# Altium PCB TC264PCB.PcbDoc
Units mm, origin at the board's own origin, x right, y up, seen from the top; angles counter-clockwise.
Board outline 100.58 x 100.35 mm, 2 copper layers (Top Layer, Bottom Layer); 82 components, 103 nets, 403 pads, 81 vias.
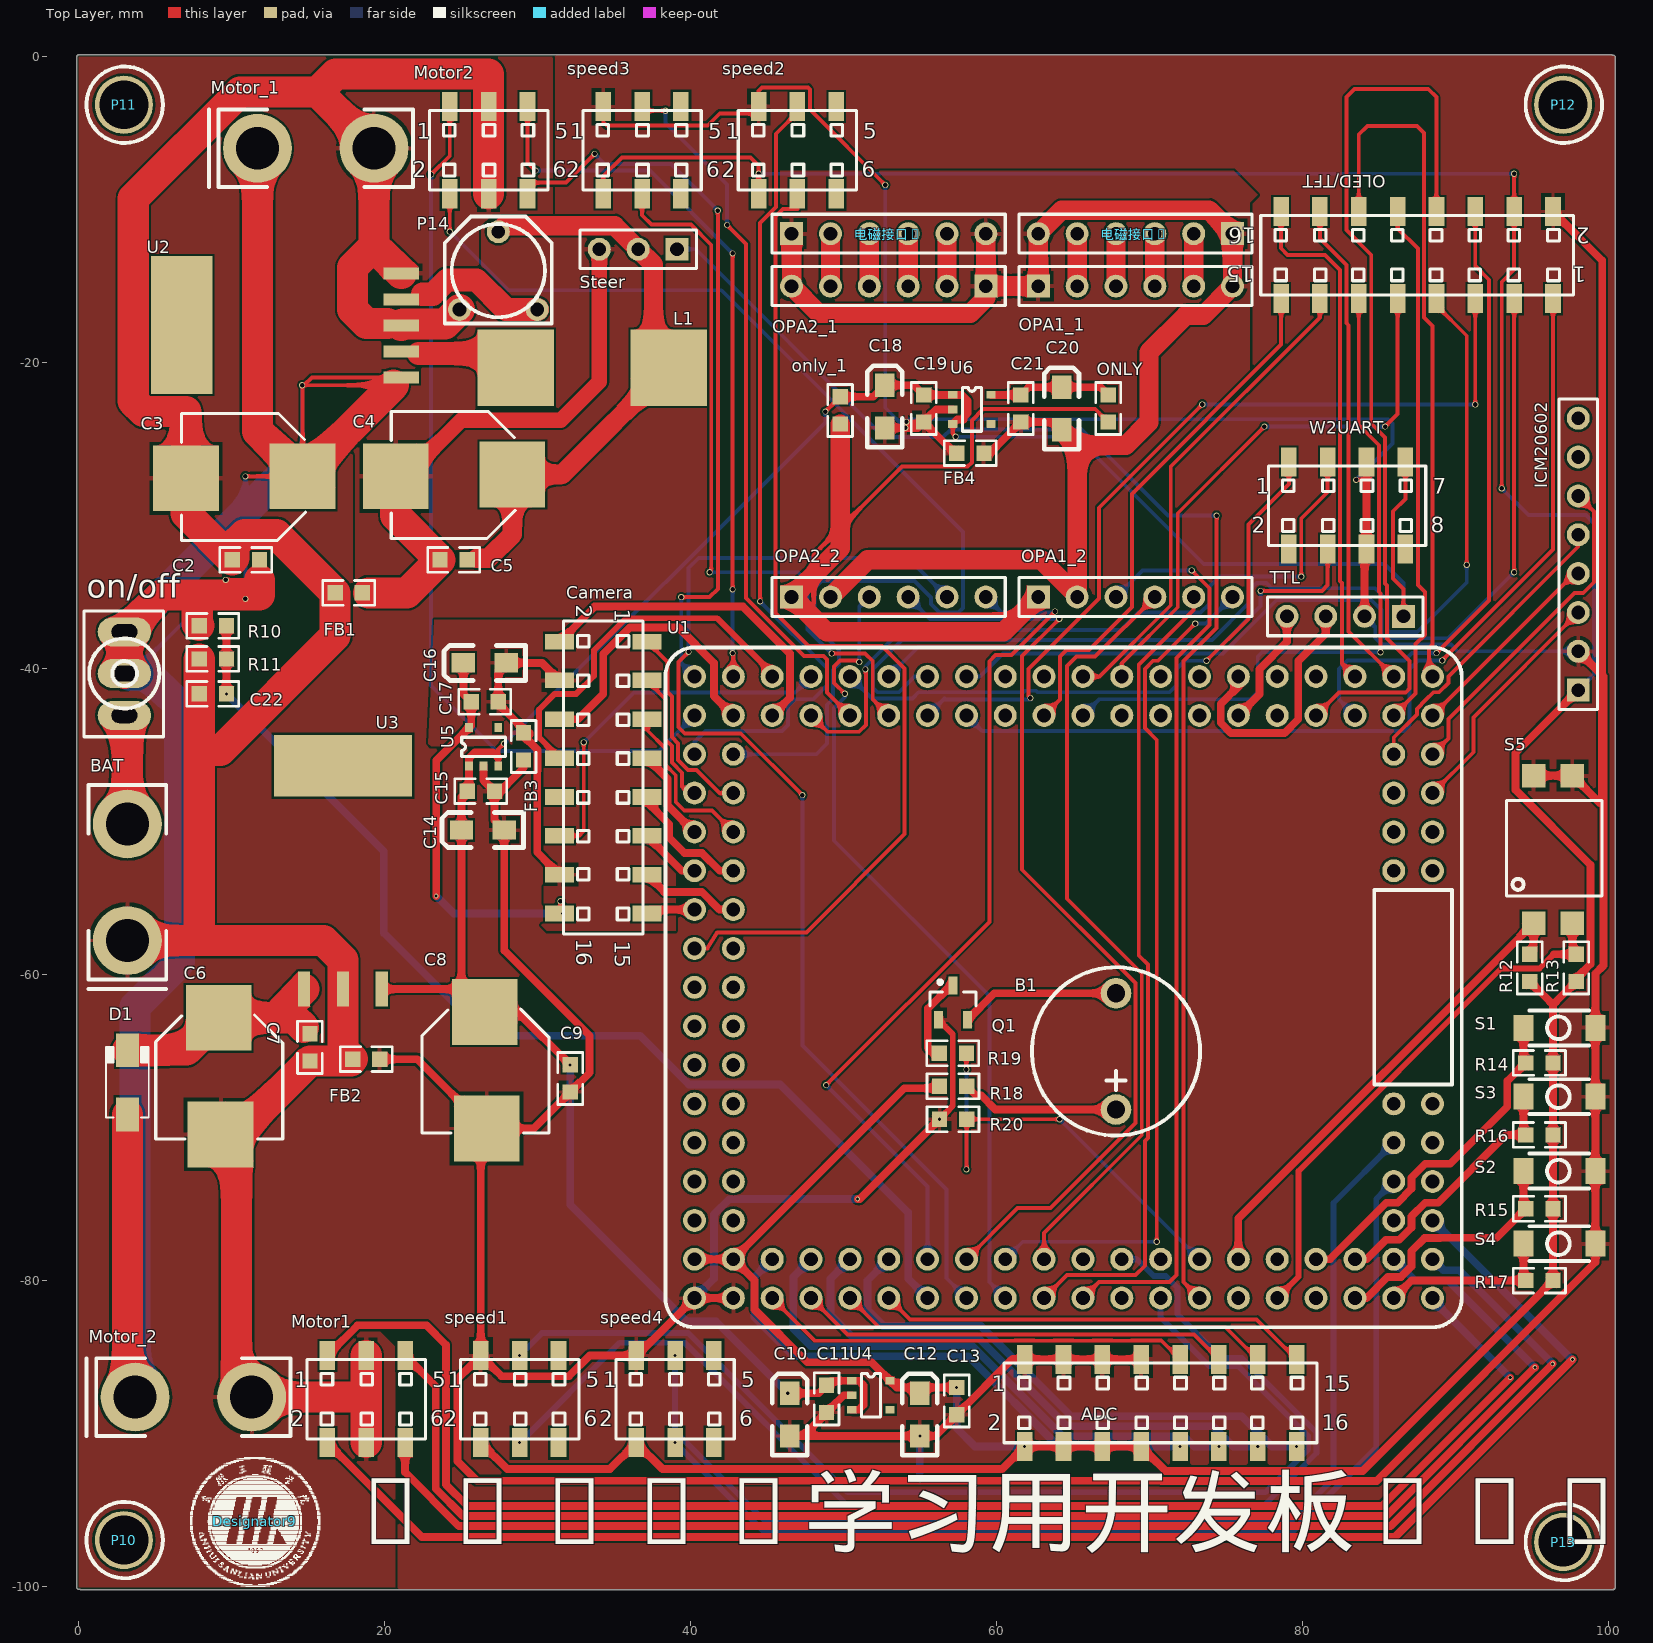
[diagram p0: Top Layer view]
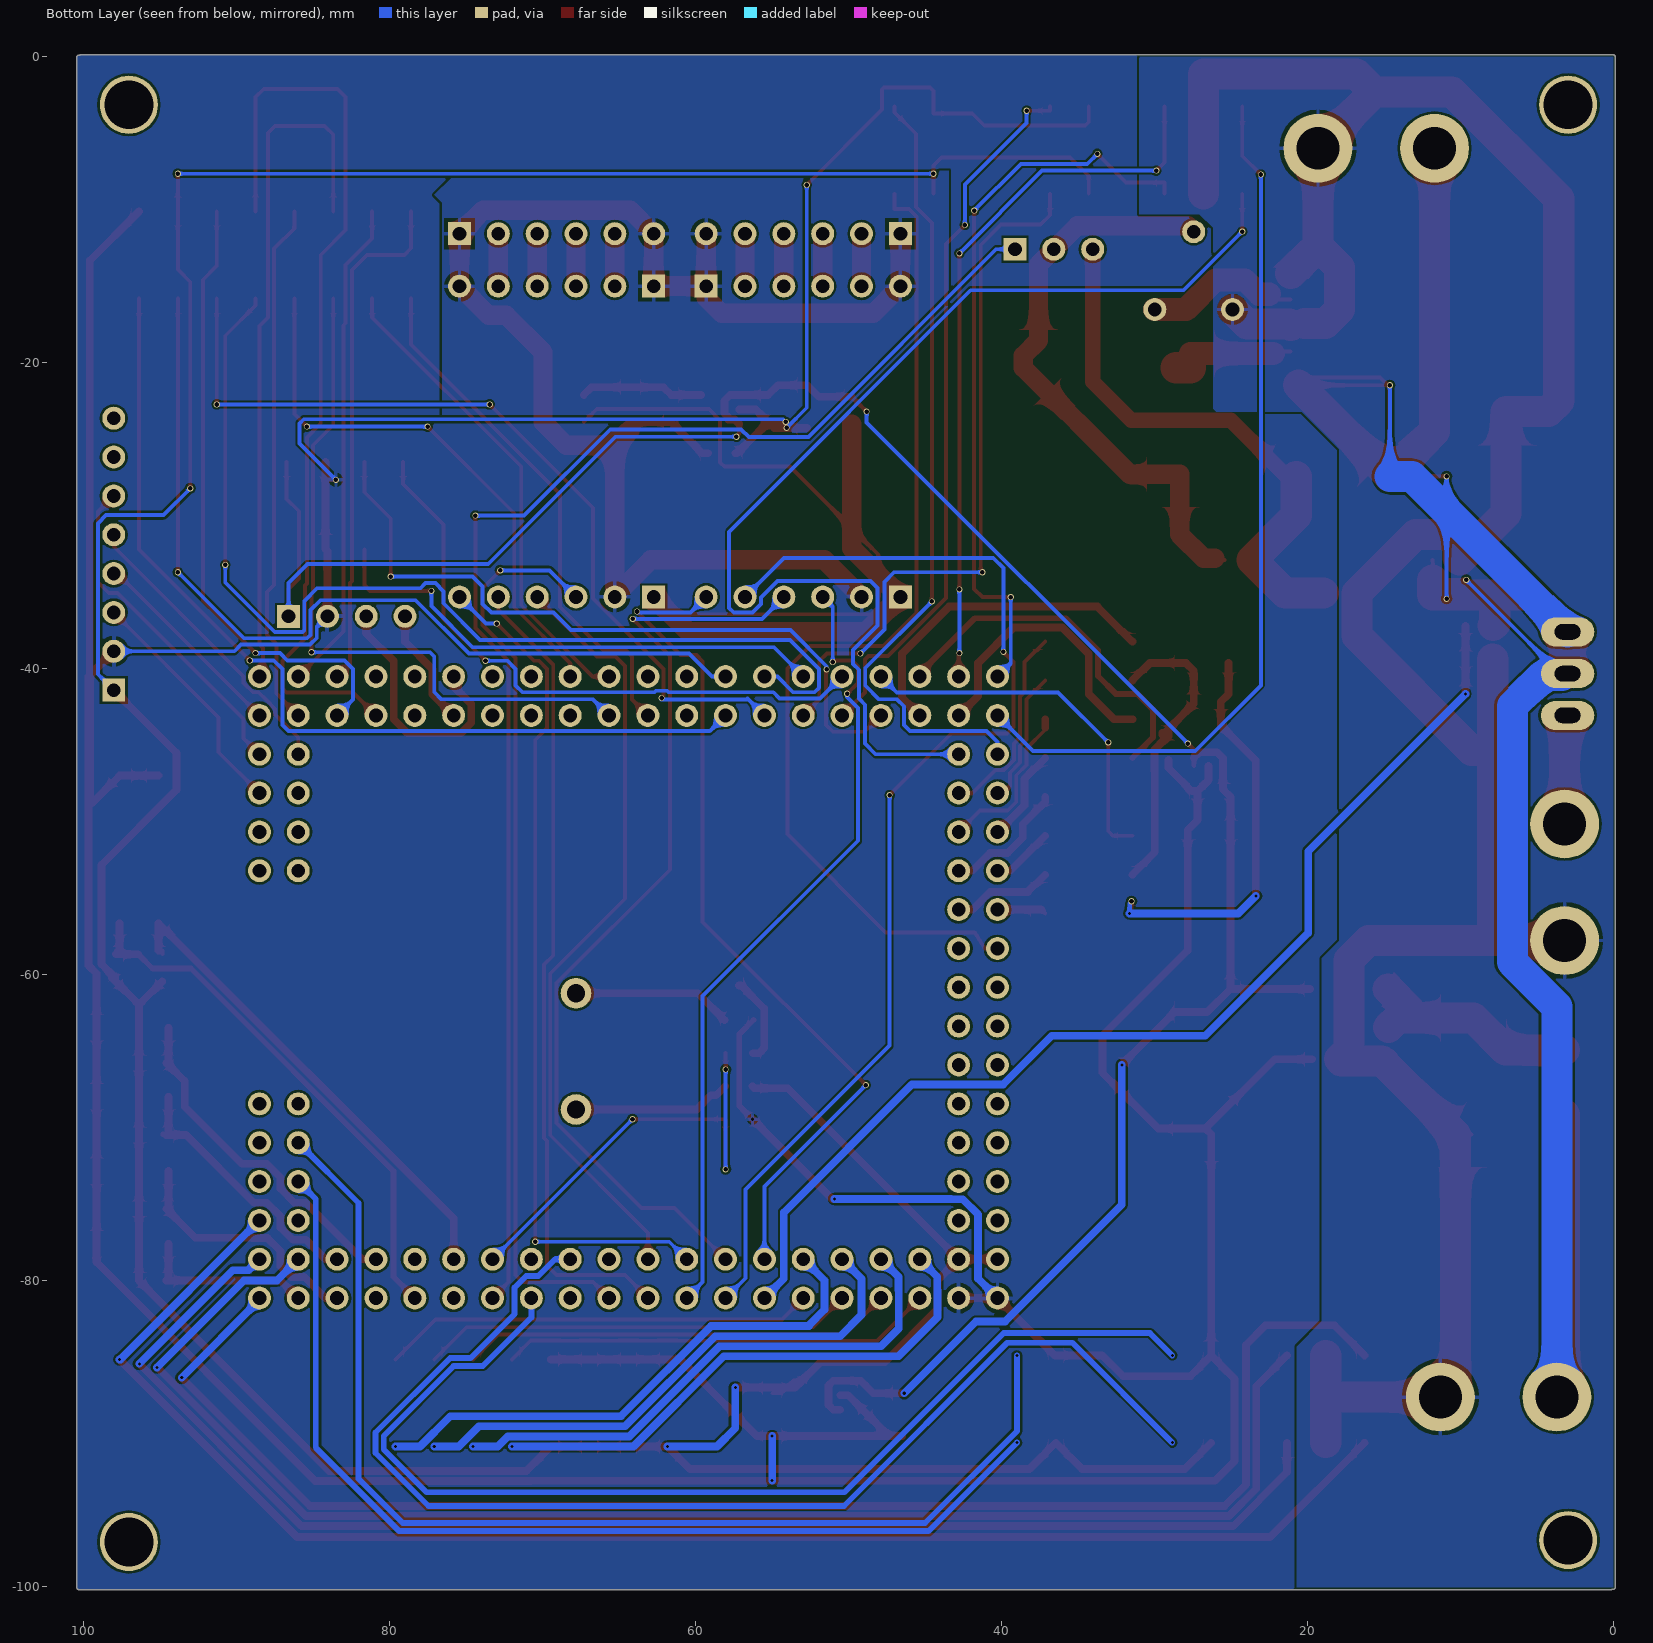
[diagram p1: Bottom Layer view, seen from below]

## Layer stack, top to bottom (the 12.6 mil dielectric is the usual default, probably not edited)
Top Solder: solder mask 0.0102, Solder Resist, Dk 3.5
Top Layer: signal copper 0.0356
Dielectric 1: dielectric 0.32, FR-4, Dk 4.8
Bottom Layer: signal copper 0.0356
Bottom Solder: solder mask 0.0102, Solder Resist, Dk 3.5

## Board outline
-0.127,-100.066 ccw(c0,-100.066) 0.046,-100.185 ccw(c0.127,-100.086) 0.127,-100.213 100.33,-100.213 ccw(c100.33,-100.086) 100.457,-100.086 100.457,-0.01 ccw(c100.33,-0.01) 100.284,0.109 ccw(c100.203,0.01) 100.203,0.137 0,0.137 ccw(c0,0.01) -0.127,0.01

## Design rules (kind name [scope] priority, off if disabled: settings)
Clearance [All] p1: gap=0.152 ignorepadtopadclearanceinfootprint=FALSE
ComponentClearance [All] p1: gap=0 collisioncheckmode=3 verticalgap=0 showdistances=FALSE
HoleSize [All] p1: absolutevalues=TRUE maxlimit=12.7 minlimit=0.025 maxpercent=80.000 minpercent=20.000
HoleToHoleClearance [All] p1: gap=0.051 allowstackedmicrovias=TRUE
MinimumSolderMaskSliver [All] p1: minsoldermaskwidth=0
PolygonConnect [All] p1: connectstyle=Relief reliefconductorwidth=0.254 reliefentries=4 polygonreliefangle="90 Angle" airgapwidth=0.254
RoutingVias [All] p1: holewidth=0.3 width=0.4 viastyle="Through Hole" minholewidth=0.3 minwidth=0.4 maxholewidth=0.3 maxwidth=0.4
SilkToSilkClearance [All] p1: silktosilkclearance=0
SilkToSolderMaskClearance [IsPad] p1: minsilkscreentomaskgap=0 clearancetoexposedcopper=TRUE
SolderMaskExpansion [All] p1: expansion=0.102
Width [All] p1: maxlimit=12.7 minlimit=0.025 preferedwidth=0.254 minimp=50.000000 maximp=50.000000 favimp=50.000000
24 further rules are at their usual default settings.

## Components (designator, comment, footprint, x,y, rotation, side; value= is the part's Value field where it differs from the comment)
ADC "Header 8X2" HDR2.54-M-LS-2x8P 70.739,-88.011 r0 top
B1 "BEEP" 9*11mm有源蜂鸣器 67.818,-65.024 r90 top
BAT "Header 2" 电源端口 3.175,-57.775 r90 top
C2 "Cap" 0603电容_ 11.049,-32.883 r0 top value=0.1uf
C3 "Cap Pol1" 470UF 10.668,-27.422 r0 top value=330uf
C4 "Cap Pol1" 470UF 24.384,-27.295 r0 top value=330uf
C5 "Cap" 0603电容_ 24.638,-32.883 r0 top value=0.1uf
C6 "Cap Pol1" 470UF 9.144,-66.792 r90 top value=220uf
C7 "Cap" 0603电容_ 15.113,-64.633 r90 top value=0.1uf
C8 "Cap Pol1" 470UF 26.543,-66.411 r90 top value=220uf
C9 "Cap" 0603电容_ 32.131,-66.665 r90 top value=0.1uf
C10 "Cap Pol2" 10UF钽电容 46.355,-88.9 r0 top value=10uf
C11 "Cap" 0603电容_ 48.895,-87.617 r90 top value=0.1uf
C12 "Cap Pol2" 10UF钽电容 54.864,-88.9 r0 top value=10uf
C13 "Cap" 0603电容_ 57.404,-87.757 r90 top value=0.1uf
C14 "Cap Pol2" 10UF钽电容 26.543,-50.673 r90 top value=10uf
C15 "Cap" 0603电容_ 26.162,-48.006 r180 top value=0.1uf
C16 "Cap Pol2" 10UF钽电容 26.67,-39.751 r90 top value=10uf
C17 "Cap" 0603电容_ 26.416,-42.164 r180 top value=0.1uf
C18 "Cap Pol2" 10UF钽电容 52.578,-22.987 r0 top value=10uf
C19 "Cap" 0603电容_ 55.245,-22.86 r90 top value=0.1uf
C20 "Cap Pol2" 10UF钽电容 64.135,-23.114 r0 top value=10uf
C21 "Cap" 0603电容_ 61.595,-22.86 r90 top value=0.1uf
C22 "Cap" 0603电容_ 8.89,-41.646 r0 top value=0.1uf
Camera "Header 8X2" HDR2.54-M-LS-2x8P 34.29,-47.117 r270 top
D1 "SS54" in5819_SLFK 3.175,-67.046 r90 top
Designator9 "Comment" 三联logo 11.519,-95.758 r0 top
FB1 "0R" 0603电阻_ 17.653,-35.042 r180 top
FB2 "0R" 0603电阻_ 18.796,-65.532 r180 top
FB3 "0R" 0603电阻_ 29.083,-45.085 r270 top
FB4 "0R" 0603电阻_ 58.293,-25.908 r180 top
ICM20602 "Header 8" HDR1X8 98.044,-41.402 r90 top
L1 "330uH" 330uH 28.575,-20.32 r0 top
Motor1 "Header 3X2" HDR2.54-M-LS-2x3P 18.796,-87.757 r0 top (schematic designator 电机接口1)
Motor2 "Header 3X2" HDR2.54-M-LS-2x3P 26.797,-6.096 r0 top (schematic designator 电机接口2)
Motor_1 "Header 2" 电源端口 11.684,-5.969 r0 top (schematic designator 供电1)
Motor_2 "Header 2" 电源端口 3.683,-87.63 r0 top (schematic designator 供电2)
OLED/TFT "Header 8X2" HDR2.54-M-LS-2x8P 87.503,-12.954 r180 top
on/off "Header 3" 小扭子开关 3.048,-40.259 r270 top
ONLY "0R" 0603电阻_ 67.31,-22.987 r90 top
only_1 "0R" 0603电阻_ 49.784,-23.114 r90 top
OPA1_1 "Header 6" HDR1X6 62.738,-14.986 r0 top
OPA1_2 "Header 6" HDR1X6 62.738,-35.306 r0 top
OPA2_1 "Header 6" HDR1X6 59.309,-14.986 r180 top
OPA2_2 "Header 6" HDR1X6 46.609,-35.306 r0 top
P10 "SMB" 螺丝孔 2.921,-97.028 r0 top
P11 "SMB" 螺丝孔 2.921,-3.175 r0 top
P12 "SMB" 螺丝孔 97.028,-3.175 r0 top
P13 "SMB" 螺丝孔 97.028,-97.155 r0 top
P14 "10K可调" 白兰可调电阻 27.432,-11.43 r0 top
Q1 "S8050" SI2302 57.15,-61.839 r90 top
R10 "200K" 0603电阻_ 8.763,-37.201 r180 top
R11 "100K" 0603电阻_ 8.763,-39.36 r0 top
R12 "4.7K" 0603电阻_ 94.869,-59.563 r270 top
R13 "4.7K" 0603电阻_ 97.917,-59.563 r270 top
R14 "4.7K" 0603电阻_ 95.504,-65.776 r0 top
R15 "4.7K" 0603电阻_ 95.504,-75.311 r0 top
R16 "4.7K" 0603电阻_ 95.504,-70.485 r0 top
R17 "4.7K" 0603电阻_ 95.504,-80.01 r0 top
R18 "10R" 0603电阻_ 57.166,-67.3 r180 top
R19 "4.7K" 0603电阻_ 57.15,-65.141 r0 top
R20 "10K" 0603电阻_ 57.166,-69.459 r0 top
S1 "" 3*4*2贴片轻触按键 94.465,-63.483 r0 top
S2 "" 3*4*2贴片轻触按键 94.465,-72.851 r0 top
S3 "" 3*4*2贴片轻触按键 94.465,-67.985 r0 top
S4 "" 3*4*2贴片轻触按键 94.465,-77.597 r0 top
S5 "拨码开关" 2pin拨码开关2.54_SMT 95.123,-56.642 r90 top
speed1 "Header 3X2" HDR2.54-M-LS-2x3P 28.829,-87.757 r0 top (schematic designator 编码器1)
speed2 "Header 3X2" HDR2.54-M-LS-2x3P 46.99,-6.096 r0 top (schematic designator 编码器2)
speed3 "Header 3X2" HDR2.54-M-LS-2x3P 36.83,-6.096 r0 top (schematic designator 编码器3)
speed4 "Header 3X2" HDR2.54-M-LS-2x3P 38.989,-87.757 r0 top (schematic designator 编码器4)
Steer "Header 3" HDR1X3 39.116,-12.573 r180 top
TTL "TTL" HDR1X4 86.614,-36.576 r180 top
U1 "TC264_CoreBoard" TC264_CoreBoard 40.259,-81.153 r90 top
U2 "LM2596S-ADJ" TO263-5 21.082,-20.955 r90 top
U3 "LM2940" LM2940-5.0 14.732,-60.95 r0 top
U4 "RT9013-33" SOT-23-5 50.546,-86.554 r0 top
U5 "RT9013-33" SOT-23-5 25.517,-46.355 r90 top
U6 "RT9013-33" SOT-23-5 57.15,-22.098 r0 top
W2UART "W2UART" HDR2.54-M-LS-2x4P 82.931,-29.337 r0 top
电磁接口1 "Header 6" HDR1X6 75.438,-11.557 r180 top
电磁接口2 "Header 6" HDR1X6 46.609,-11.557 r0 top

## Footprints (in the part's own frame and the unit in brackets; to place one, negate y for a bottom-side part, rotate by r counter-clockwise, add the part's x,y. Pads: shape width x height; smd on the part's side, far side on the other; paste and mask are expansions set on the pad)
2pin拨码开关2.54_SMT [mm]
  rect 1.54x1.54 smd: 1(0,0) 2(0,-2.54) 3(9.652,-2.54) 4(9.652,0)
  silkscreen extent 1.78,-4.47 8.03,1.78, body extent 0.12,-4.9 9.19,2.16, height 4.45
3*4*2贴片轻触按键 [mm]
  rect 1.3x1.7 smd: 1(0,0) 2(4.699,0)
  silkscreen extent 0.38,-1.14 4.28,1.14, body extent -0.12,-1.14 4.78,1.14, height 2
9*11mm有源蜂鸣器 [mm]
  round 2 hole 1.2: 1(-3.8,0) 2(3.8,0)
  silkscreen extent -5.5,-5.5 5.5,5.5
10UF钽电容 [mil]
  rect 50x60 smd: 1(5,60) 2(5,-50)
  silkscreen extent -40,-100 50,110, body extent -26,-58 36,68, height 63
330uH [mm]
  rect 5x5 smd: 1(0,0) 2(10,0)
470UF [mm]
  rect 4.3x4.3 smd: 1(3.962,0) 2(-3.658,-0.127)
  silkscreen extent -3.96,-4.19 4.15,4.11, body extent -5,-4.41 4.7,4.09, height 10.3
0603电容_ [mm]
  rect 1x1 smd: 1(-1.016,0) 2(0.762,0)
  silkscreen extent -1.83,-0.81 1.57,0.81, body extent -0.92,-0.38 0.68,0.42, height 0.3
0603电阻_ [mm]
  rect 1x1 smd: 1(0.889,0) 2(-0.889,0)
  silkscreen extent -1.7,-0.81 1.7,0.81, body extent -0.8,-0.4 0.8,0.4, height 0.3
HDR1X3 [mm] "Connector; Header; 3 Position"
  rect 1.5x1.5 hole 0.9: 1(0,0)
  round 1.5 hole 0.9: 2(2.54,0) 3(5.08,0)
  silkscreen extent -1.27,-1.27 6.35,1.27
HDR1X4 [mm] "Connector; Header; 4 Position"
  rect 1.5x1.5 hole 0.9: 1(0,0)
  round 1.5 hole 0.9: 2(2.54,0) 3(5.08,0) 4(7.62,0)
  silkscreen extent -1.27,-1.27 8.89,1.27
HDR1X6 [mm] "Connector; Header; 6 Position"
  rect 1.5x1.5 hole 0.9: 1(0,0)
  round 1.5 hole 0.9: 2(2.54,0) 3(5.08,0) 4(7.62,0) 5(10.16,0) 6(12.7,0)
  silkscreen extent -1.27,-1.27 13.97,1.27
HDR1X8 [mm] "Connector; Header; 8 Position"
  rect 1.5x1.5 hole 0.9: 1(0,0)
  round 1.5 hole 0.9: 2(2.54,0) 3(5.08,0) 4(7.62,0) 5(10.16,0) 6(12.7,0) 7(15.24,0) 8(17.78,0)
  silkscreen extent -1.27,-1.27 19.05,1.27
HDR2.54-M-LS-2x3P [mm] "脚距：2.54mm，贴片双排母"
  rect 1.02x1.9 smd: 1(-2.54,2.85) 2(-2.54,-2.85) 3(0,2.85) 4(0,-2.85) 5(2.54,2.85) 6(2.54,-2.85)
  silkscreen extent -3.87,-2.6 3.87,2.6, body extent -3.84,-3.2 3.84,3.2, height 5.15
HDR2.54-M-LS-2x4P [mm] "脚距：2.54mm，贴片双排母"
  rect 1.02x1.9 smd: 1(-3.81,2.85) 2(-3.81,-2.85) 3(-1.27,2.85) 4(-1.27,-2.85) 5(1.27,2.85) 6(1.27,-2.85) 7(3.81,2.85) 8(3.81,-2.85)
  silkscreen extent -5.15,-2.6 5.14,2.6, body extent -5.11,-3.2 5.11,3.2, height 5.15
HDR2.54-M-LS-2x8P [mm] "脚距：2.54mm，贴片双排母"
  rect 1.02x1.9 smd: 1(-8.89,2.85) 2(-8.89,-2.85) 3(-6.35,2.85) 4(-6.35,-2.85) 5(-3.81,2.85) 6(-3.81,-2.85) 7(-1.27,2.85) 8(-1.27,-2.85) 9(1.27,2.85) 10(1.27,-2.85) 11(3.81,2.85) 12(3.81,-2.85) 13(6.35,2.85) 14(6.35,-2.85) 15(8.89,2.85) 16(8.89,-2.85)
  silkscreen extent -10.23,-2.6 10.22,2.6, body extent -10.19,-3.2 10.19,3.2, height 5.15
in5819_SLFK [mm] "JEDEC DO214 variation AC. SMA"
  rect 2.2x1.5 smd: 1(-2.1,0) 2(2.1,0)
  silkscreen extent -2.3,-1.4 2.3,1.4, body extent -2.6,-1.3 2.6,1.3, height 2.42
LM2940-5.0 [mm]
  rect 9x4 smd: 0(2.54,14.605)
  rect 0.8x2.3 smd: 1(0,0) 2(2.54,0) 3(5.08,0)
  body extent -2.46,-0.29 7.54,15.38, height 4.78
SI2302 [mm] "MOSFET-N"
  rect 1.15x0.6 smd: 1(-1.128,0.934) 2(-1.128,-0.966) 3(1.122,-0.016)
  silkscreen extent -0.2,-1.52 1.47,1.48, body extent -0.7,-1.52 0.7,1.48, height 1.1
SOT-23-5 [mm]
  rect 0.6x0.5 smd: 1(0,0) 2(0,-0.95) 3(0,-1.9) 4(2.5,-1.9) 5(2.5,0)
  silkscreen extent 0.63,-2.38 1.87,0.48, body extent 0.25,-2.45 2.25,0.6, height 0.51
TC264_CoreBoard [mm] "逐飞科技TC264核心板"
  round 1.5 hole 0.9: 1(0,0) 2(2.54,0) 3(0,-2.54) 4(2.54,-2.54) 5(0,-5.08) 6(2.54,-5.08) 7(0,-7.62) 8(2.54,-7.62) 9(0,-10.16) 10(2.54,-10.16) 11(0,-12.7) 12(2.54,-12.7) 13(0,-15.24) 14(2.54,-15.24) 15(0,-17.78) 16(2.54,-17.78) 17(0,-20.32) 18(2.54,-20.32) 19(0,-22.86) 20(2.54,-22.86) 21(0,-25.4) 22(2.54,-25.4) 23(0,-27.94) 24(2.54,-27.94) 25(0,-30.48) 26(2.54,-30.48) 27(0,-33.02) 28(2.54,-33.02) 29(0,-35.56) 30(2.54,-35.56) 31(0,-38.1) 32(2.54,-38.1) 33(0,-40.64) 34(2.54,-40.64) 35(0,-43.18) 36(2.54,-43.18) 37(0,-45.72) 38(2.54,-45.72) 39(0,-48.26) 40(2.54,-48.26) 41(5.08,-48.26) 42(5.08,-45.72) 43(7.62,-48.26) 44(7.62,-45.72) 45(10.16,-48.26) 46(10.16,-45.72) 47(12.7,-48.26) 48(12.7,-45.72) 49(27.94,-45.72) 50(27.94,-48.26) 51(30.48,-45.72) 52(30.48,-48.26) 53(33.02,-45.72) 54(33.02,-48.26) 55(35.56,-45.72) 56(35.56,-48.26) 57(38.1,-48.26) 58(40.64,-48.26) 59(38.1,-45.72) 60(40.64,-45.72) 61(38.1,-43.18) 62(40.64,-43.18) 63(38.1,-40.64) 64(40.64,-40.64) 65(38.1,-38.1) 66(40.64,-38.1) 67(38.1,-35.56) 68(40.64,-35.56) 69(38.1,-33.02) 70(40.64,-33.02) 71(38.1,-30.48) 72(40.64,-30.48) 73(38.1,-27.94) 74(40.64,-27.94) 75(38.1,-25.4) 76(40.64,-25.4) 77(38.1,-22.86) 78(40.64,-22.86) 79(38.1,-20.32) 80(40.64,-20.32) 81(38.1,-17.78) 82(40.64,-17.78) 83(38.1,-15.24) 84(40.64,-15.24) 85(38.1,-12.7) 86(40.64,-12.7) 87(38.1,-10.16) 88(40.64,-10.16) 89(38.1,-7.62) 90(40.64,-7.62) 91(38.1,-5.08) 92(40.64,-5.08) 93(38.1,-2.54) 94(40.64,-2.54) 95(38.1,0) 96(40.64,0) 97(35.56,-2.54) 98(35.56,0) 99(33.02,-2.54) 100(33.02,0) 101(30.48,-2.54) 102(30.48,0) 103(27.94,-2.54) 104(27.94,0) 105(25.4,-2.54) 106(25.4,0) 107(22.86,-2.54) 108(22.86,0) 109(20.32,-2.54) 110(20.32,0) 111(17.78,-2.54) 112(17.78,0) 113(15.24,-2.54) 114(15.24,0) 115(12.7,-2.54) 116(12.7,0) 117(10.16,-2.54) 118(10.16,0) 119(7.62,-2.54) 120(7.62,0) 121(5.08,-2.54) 122(5.08,0)
  silkscreen extent -1.91,-50.16 42.55,1.91
TO263-5 [mm]
  rect 9x4 smd: 0(3.429,14.351)
  rect 0.8x2.3 smd: 1(0,0) 2(1.7,0) 3(3.4,0) 4(5.1,0) 5(6.8,0)
  body extent -1.57,-0.54 8.43,15.13, height 4.83
三联logo [mm]
  silkscreen extent -4.24,-4.24 4.27,4.19
小扭子开关 [mm]
  oval 1.9x3.5 hole 1 slot 1.7 at 90 deg: 1(2.794,-0.063) 2(0.064,-0.063) 3(-2.667,-0.064)
  silkscreen extent -4.04,-2.71 4.19,2.49, body extent -4.14,-2.81 4.29,2.6, height 24
电源端口 [mm]
  round 4.5 hole 2.8: 1(0,0) 2(7.62,0)
  silkscreen extent -3.17,-2.54 10.16,2.54
白兰可调电阻 [mm]
  round 1.5 hole 0.9: 1(-2.54,-5.08) 2(2.54,-5.08) 3(0,0)
  silkscreen extent -3.51,-6.01 3.49,0.99, body extent -3.51,-6.01 3.5,0.99, height 5.84
螺丝孔 [mm]
  round 3.8 hole 3.2: 0(0.025,0.051)
  silkscreen extent -2.42,-2.45 2.58,2.55, body extent -2.72,-2.75 2.88,2.85, height 2.37

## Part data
ADC Camera OLED/TFT: "Header, 8-Pin, Dual row"
B1: library part "Header 2", "Header, 2-Pin"
BAT Motor_1 Motor_2: "Header, 2-Pin"
C2 C5 C7 C9 C11 C13 C15 C17 C19 C21 C22: "Capacitor"
C3 C4 C6 C8: "Polarized Capacitor (Radial)"
C10 C12 C14 C16 C18 C20: "Polarized Capacitor (Axial)"
D1: library part "Diode 1N5404", "3 Amp General Purpose Rectifier"
FB1 FB2 FB3 FB4 ONLY only_1 R10 R11 R12 R13 R14 R15 R16 R17 R18 R19 R20: library part Res2, "Resistor"
ICM20602: "Header, 8-Pin"
Motor1 Motor2 speed1 speed2 speed3 speed4: "Header, 3-Pin, Dual row"
on/off Steer: "Header, 3-Pin"
OPA1_1 OPA1_2 OPA2_1 OPA2_2 电磁接口1 电磁接口2: "Header, 6-Pin"
P10 P11 P12 P13: "SMB Straight Connector"
P14: library part "Header 3", "Header, 3-Pin"
Q1: library part 2N3904, "NPN General Purpose Amplifier"
S1 S2 S3 S4: library part SW-PB, "Switch"
S5: library part "SW DIP-2", "DIP Switch, 2 Position, SPST"
TTL: library part "Header 4", "Header, 4-Pin"
U1: "逐飞科技TC264核心板"
U2: library part LM2596S
W2UART: library part "Header 4X2", "Header, 4-Pin, Dual row"

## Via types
v1: diameter 0.4, hole 0.3, Top Layer to Bottom Layer, 58 vias
v2: diameter 0.3/0.1 (per signal layer), hole 0.2, Top Layer to Bottom Layer, 23 vias

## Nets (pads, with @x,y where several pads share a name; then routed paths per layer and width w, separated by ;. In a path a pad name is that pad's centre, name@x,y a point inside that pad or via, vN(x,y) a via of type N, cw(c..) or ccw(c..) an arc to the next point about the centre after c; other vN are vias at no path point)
00.0: Camera.1 U1.99 | length 13.1
  Top Layer w0.254: Camera.1 38.481,-39.568 38.481,-41.533 38.776,-41.828 38.776,-44.478 39.182,-44.885 39.182,-45.972 39.833,-46.622 40.386,-46.622 41.897,-48.133 U1.99
00.1: Camera.3 U1.100 | length 8.9
  Top Layer w0.254: Camera.3 38.369,-41.996 38.369,-44.647 38.776,-45.053 38.776,-46.14 39.436,-46.801 39.436,-47.691 39.878,-48.133 U1.100
00.2: Camera.5 U1.101 | length 11.2
  Top Layer w0.254: 37.14,-43.856 37.14,-43.992 38.369,-45.221 38.369,-46.309 39.03,-46.969 39.03,-48.719 39.587,-49.276 41.402,-49.276 U1.101
  Top Layer w0.508: 37.14,-43.856 Camera.5 ; U1.101@42.418,-50.673 U1.101
00.3: Camera.7 U1.102 | length 6.1
  Top Layer w0.508: Camera.7 38.496,-47.203 38.496,-48.94 40.23,-50.673 U1.102
00.4: Camera.9 U1.103 | length 8.4
  Top Layer w0.508: Camera.9 37.14,-48.697 38.608,-50.165 38.608,-51.054 39.611,-52.057 40.754,-52.057 41.91,-53.213 U1.103
00.5: Camera.11 U1.104 | length 4.1
  Top Layer w0.508: Camera.11 39.426,-53.213 U1.104
00.6: Camera.13 U1.105 | length 6.6
  Top Layer w0.508: Camera.13 38.27,-54.597 40.738,-54.597 41.894,-55.753 U1.105
00.7: Camera.15 U1.106 | length 3.2
  Top Layer w0.254: Camera.15 Camera.15@37.394,-55.753
  Top Layer w0.508: Camera.15@37.394,-55.753 U1.106
00.9: speed2.4 U1.108 | length 66.3
  Top Layer w0.254: U1.108 41.097,-58.293 41.758,-57.242 47.574,-57.242 54,-50.815 54,-39.995 52.522,-38.517 47.721,-38.517 45.568,-36.363 45.568,-10.42 46.041,-9.947 46.99,-9.947 speed2.4
02.0: Camera.12 U1.90 | length 24.2
  Top Layer w0.254: Camera.12 32.715,-50.927 33.02,-50.622 v1(33.02,-44.821)
  Bottom Layer w0.254: v1(33.02,-44.821) 36.297,-41.544 46.848,-41.544 U1.90
02.1: Camera.2 U1.91 | length 21.8
  Top Layer w0.508: Camera.2 33.726,-35.941 43.434,-35.941 46.495,-39.002 46.495,-41.897 U1.91
02.2: Camera.8 U1.92 | length 24.1
  Top Layer w0.381: Camera.8 30.099,-44.506 30.099,-42.672 31.125,-41.646 32.522,-41.646 33.693,-40.475 33.693,-38.795 35.785,-36.703 41.738,-36.703 45.339,-40.304 U1.92
02.3: Camera.6 U1.93 | length 19
  Top Layer w0.508: Camera.6 32.639,-43.307 34.29,-41.656 34.29,-39.042 36.022,-37.311 39.216,-37.311 41.529,-39.624 41.529,-41.783 U1.93
02.4: Motor2.5 U1.94 | length 47.2
  Top Layer w0.254: Motor2.5 29.337,-6.899 v1(29.87,-7.432) ; v1(42.748,-38.979) 42.799,-39.03 U1.94 ; v1(42.748,-34.813) v1(42.748,-12.842)
  Bottom Layer w0.254: v1(29.87,-7.432) 37.338,-7.432 v1(42.748,-12.842) ; v1(42.748,-38.979) v1(42.748,-34.813)
02.5: Motor2.1 U1.95 | length 58.3
  Top Layer w0.254: v1(23.038,-7.686) 24.257,-6.467 Motor2.1
  Bottom Layer w0.254: v1(23.038,-7.686) 23.038,-41.087 27.33,-45.38 37.932,-45.38 U1.95
02.6: Motor2.6 U1.96 | length 48.4
  Top Layer w0.254: Motor2.6 29.337,-8.22 31.852,-8.22 v1(33.731,-6.34) ; v1(39.395,-35.321) 41.25,-35.321 41.783,-34.788 v1(41.783,-10.048)
  Bottom Layer w0.254: v1(33.731,-6.34) 34.392,-7 38.735,-7 v1(41.783,-10.048) ; v1(39.395,-35.321) 39.395,-39.649 U1.96
02.7: Motor2.2 U1.97 | length 77.9
  Top Layer w0.254: v1(24.257,-11.42) Motor2.2
  Bottom Layer w0.254: v1(24.257,-11.42) 28.092,-15.255 42.012,-15.255 57.81,-31.054 57.81,-36.033 57.506,-36.337 56.286,-36.337 55.728,-35.779 55.728,-35.349 54.633,-34.255 48.565,-34.255 48.108,-34.712 48.108,-37.176 49.708,-38.776 49.708,-39.69 49.327,-40.071 49.327,-41.951 48.92,-42.357 48.92,-44.897 48.225,-45.593 U1.97
02.8: speed2.3 U1.98 | length 52.4
  Top Layer w0.254: v1(44.552,-35.601) 44.552,-10.861 45.593,-9.82 45.593,-5.019 46.99,-3.622 speed2.3
  Bottom Layer w0.254: U1.98 40.259,-44.796 40.97,-44.084 45.974,-44.084 46.38,-43.678 46.38,-42.459 46.838,-42.002 48.006,-42.002 48.908,-41.099 48.908,-39.958 v1(44.552,-35.601)
10.1: speed3.4 U1.85 | length 47
  Top Layer w0.254: speed3.4 36.83,-10.353 37.44,-10.963 40.03,-10.963 41.354,-12.287 41.354,-33.591 v1(41.25,-33.696) ; v1(49.225,-39.004) 51.41,-39.004 51.918,-39.512 51.918,-42.012 U1.85
  Bottom Layer w0.254: v1(41.25,-33.696) 47.015,-33.696 47.65,-34.331 47.65,-37.43 v1(49.225,-39.004)
10.2: U1.86 W2UART.4 | length 34.1
  Top Layer w0.254: v1(77.279,-34.915) 81.28,-34.915 81.661,-34.534 W2UART.4
  Bottom Layer w0.254: U1.86 54.874,-38.598 74.577,-38.598 77.279,-35.896 v1(77.279,-34.915)
10.3: speed3.3 U1.87 | length 47.1
  Top Layer w0.254: speed3.3 36.83,-3.521 v1(38.354,-3.521) ; v1(42.393,-10.988) 43.637,-12.233 43.637,-35.39 47.43,-39.182 48.692,-39.182 48.92,-39.411 48.92,-41.554 U1.87
  Bottom Layer w0.254: v1(38.354,-3.521) 38.354,-4.308 42.393,-8.347 v1(42.393,-10.988)
10.5: U1.88 W2UART.1 | length 40.9
  Top Layer w0.254: v1(73.74,-39.484) 76.479,-36.744 76.479,-30.572 79.121,-27.93 W2UART.1
  Bottom Layer w0.254: U1.88 51.855,-41.949 54.512,-41.949 54.918,-41.542 61.773,-41.542 61.876,-41.439 62.589,-41.439 62.693,-41.542 71.323,-41.542 71.768,-41.097 71.768,-40.02 72.305,-39.484 v1(73.74,-39.484)
10.6: U1.89 W2UART.3 | length 47.9
  Top Layer w0.254: U1.89 48.951,-44.125 51.013,-44.125 51.46,-43.678 51.46,-40.071 v1(51.435,-40.046) ; v1(79.934,-33.975) 79.934,-30.191 81.661,-28.463 W2UART.3
  Bottom Layer w0.254: v1(51.435,-40.046) 51.435,-39.843 53.797,-37.48 68.148,-37.48 69.293,-36.335 73.355,-36.335 73.927,-35.763 73.927,-34.622 74.574,-33.975 v1(79.934,-33.975)
11.9: OLED/TFT.1 U1.81 | length 62.3
  Top Layer w0.254: v1(89.148,-39.462) 96.393,-32.217 OLED/TFT.1
  Bottom Layer w0.254: U1.81 59.07,-44.084 86.614,-44.084 87.02,-43.678 87.02,-40.02 87.579,-39.462 v1(89.148,-39.462)
11.10: OLED/TFT.3 U1.82 | length 59.5
  Top Layer w0.254: v1(93.853,-33.696) OLED/TFT.3
  Bottom Layer w0.254: U1.82 58.915,-40.513 60.423,-39.004 74.828,-39.004 78.308,-35.525 84.531,-35.525 85.178,-36.172 85.178,-37.785 85.405,-38.012 89.537,-38.012 v1(93.853,-33.696)
11.11: OLED/TFT.5 U1.83 | length 56
  Top Layer w0.254: v1(62.223,-41.919) 62.09,-41.785 62.09,-40.02 66.7,-35.41 66.7,-29.479 v1(73.457,-22.723) ; v1(91.313,-22.723) OLED/TFT.5
  Bottom Layer w0.254: U1.83 56.601,-41.951 56.674,-42.024 62.217,-42.024 62.223,-42.017 v1(62.223,-41.919) ; v1(73.457,-22.723) v1(91.313,-22.723)
11.12: OLED/TFT.7 U1.84 | length 70.1
  Top Layer w0.254: OLED/TFT.7 88.773,-16.246 90.754,-18.227 v1(90.754,-33.213)
  Bottom Layer w0.254: U1.84 54.651,-40.513 53.621,-41.542 52.222,-41.542 51.93,-41.25 51.93,-40.02 53.835,-38.115 74.084,-38.115 76.479,-35.72 76.479,-34.94 77.013,-34.407 77.648,-34.407 77.978,-34.737 84.746,-34.737 85.585,-35.575 85.585,-37.48 85.71,-37.605 87.518,-37.605 90.754,-34.37 v1(90.754,-33.213)
13.0: OLED/TFT.9 U1.74 | length 36.8
  Top Layer w0.254: U1.74 68.199,-39.639 71.857,-35.982 71.857,-29.835 v1(77.521,-24.171) ; v1(85.42,-24.171) 86.233,-23.358 OLED/TFT.9
  Bottom Layer w0.254: v1(77.521,-24.171) v1(85.42,-24.171)
13.1: OLED/TFT.11 U1.75 | length 46.2
  Top Layer w0.254: OLED/TFT.11 83.693,-24.069 85.014,-25.39 85.014,-34.969 85.115,-35.071 v1(85.115,-38.928)
  Bottom Layer w0.254: U1.75 66.71,-42.002 76.606,-42.002 77.089,-41.519 77.089,-39.208 77.368,-38.928 v1(85.115,-38.928)
13.2: OLED/TFT.13 U1.76 | length 31.8
  Top Layer w0.254: U1.76 66.741,-40.513 71.399,-35.855 71.399,-26.787 81.153,-17.033 OLED/TFT.13
13.3: OLED/TFT.15 U1.77 | length 34.5
  Top Layer w0.254: U1.77 64.16,-42.012 64.16,-39.208 64.595,-38.773 66.043,-38.773 68.859,-35.956 68.859,-28.565 78.613,-18.811 OLED/TFT.15
14.0: TTL.4 U1.67 | length 7.8
  Top Layer w0.508: U1.67 77.203,-41.669 77.203,-40.034 78.994,-38.243 TTL.4
14.1: TTL.3 U1.68 | length 16.7
  Top Layer w0.508: U1.68 75.819,-41.148 74.663,-42.304 74.663,-43.532 75.34,-44.209 78.838,-44.209 79.743,-43.305 79.743,-39.497 81.534,-37.706 TTL.3
15.0: OLED/TFT.12 U1.58 | length 45.8
  Top Layer w0.254: OLED/TFT.12 83.693,-5.07 84.252,-4.511 87.503,-4.511 87.96,-4.968 87.96,-17.033 88.519,-17.592 88.519,-38.43 88.291,-38.658 88.291,-39.941 88.519,-39.941 U1.58
15.1: OLED/TFT.10 U1.59 | length 34.5
  Top Layer w0.254: U1.59 87.415,-41.617 87.415,-38.381 88.012,-37.784 88.012,-34.992 87.554,-34.534 87.554,-12.538 86.233,-11.217 OLED/TFT.10
15.2: OLED/TFT.14 U1.60 | length 32.4
  Top Layer w0.254: OLED/TFT.14 81.153,-11.877 82.88,-13.604 82.88,-17.389 83.033,-17.541 83.033,-37.567 U1.60
15.3: OLED/TFT.6 U1.61 | length 40.9
  Top Layer w0.254: v1(88.773,-38.979) 92.202,-35.55 92.202,-14.57 91.313,-13.681 OLED/TFT.6
  Bottom Layer w0.254: U1.61 82.398,-42.012 82.398,-40.02 82.956,-39.462 86.698,-39.462 87.181,-38.979 v1(88.773,-38.979)
15.4: OLED/TFT.16 U1.62 | length 33.8
  Top Layer w0.254: OLED/TFT.16 78.613,-12.512 79.045,-12.944 81.483,-12.944 82.474,-13.935 82.474,-34.28 82.601,-34.407 82.601,-39.675 U1.62
15.5: OLED/TFT.8 U1.63 | length 61
  Top Layer w0.254: U1.63 82.408,-41.544 86.766,-41.544 87.008,-41.302 87.008,-39.487 85.547,-38.026 85.547,-34.559 85.42,-34.432 85.42,-24.882 84.506,-23.968 84.506,-12.944 82.88,-11.318 82.88,-2.632 83.414,-2.098 88.24,-2.098 88.773,-2.632 OLED/TFT.8
20.0: speed4.4 U1.44 | length 68.4
  Bottom Layer w0.381: v2(38.989,-90.607) 44.775,-96.393 79.375,-96.393 84.836,-90.932 84.836,-74.676 U1.44
20.3: speed4.3 U1.46 | length 75.3
  Bottom Layer w0.381: v2(38.989,-84.907) 38.989,-89.853 44.996,-95.86 79.146,-95.86 82.042,-92.964 82.042,-74.93 U1.46
20.11: ICM20602.3 U1.54 | length 15.8
  Top Layer w0.254: U1.54 91.186,-45.466 91.186,-43.18 ICM20602.3
20.12: ICM20602.5 U1.55 | length 19.6
  Top Layer w0.254: U1.55 85.979,-44.509 87.49,-42.998 87.49,-42.627 88.093,-42.024 88.574,-41.542 88.945,-41.542 89.548,-40.939 89.548,-40.515 98.044,-32.02 ICM20602.5
20.13: ICM20602.6 U1.56 | length 22
  Top Layer w0.254: U1.56 89.548,-44.564 89.548,-43.294 97.79,-35.052 98.37,-35.052 99.073,-34.349 99.073,-29.731 ICM20602.6
20.14: ICM20602.4 U1.57 | length 13.4
  Top Layer w0.254: U1.57 97.79,-33.782 ICM20602.4
21.2: Motor1.5 U1.38 | length 98.3
  Top Layer w0.508: Motor1.5 23.343,-86.914 23.343,-93.619 25.126,-95.402 85.491,-95.402 v2(95.209,-85.684)
  Bottom Layer w0.508: U1.38 87.363,-79.997 89.522,-79.997 v2(95.209,-85.684)
21.3: Motor1.1 U1.39 | length 99.2
  Top Layer w0.508: Motor1.1 18.232,-82.931 22.733,-82.931 24.003,-84.201 24.003,-93.345 25.4,-94.742 85.217,-94.742 v2(93.599,-86.36)
  Bottom Layer w0.508: U1.39 88.519,-81.28 v2(93.599,-86.36)
21.4: Motor1.6 U1.40 | length 93.5
  Top Layer w0.508: Motor1.6 21.336,-92.546 24.853,-96.063 85.764,-96.063 v2(96.374,-85.452)
  Bottom Layer w0.508: U1.40 89.242,-79.336 90.258,-79.336 v2(96.374,-85.452)
21.5: Motor1.2 U1.41 | length 101.7
  Top Layer w0.508: Motor1.2 22.423,-96.774 86.059,-96.774 v2(97.667,-85.165)
  Bottom Layer w0.508: U1.41 97.611,-85.165 v2(97.667,-85.165)
22.0: R14.2 S1.1 U1.34 | length 22.8
  Top Layer w0.508: U1.34 81.804,-78.613 85.5,-74.917 86.231,-74.917 87.135,-74.012 87.135,-73.281 88.04,-72.377 89.675,-72.377 93.408,-68.644 93.408,-66.967 94.599,-65.776 R14.2 94.465,-65.626 S1.1
22.1: R15.2 S2.1 U1.35 | length 16.7
  Top Layer w0.508: U1.35 84.201,-81.153 85.585,-79.769 86.458,-79.769 87.135,-79.092 87.135,-78.092 87.998,-77.229 88.998,-77.229 89.011,-77.216 92.71,-77.216 R15.2 94.465,-75.161 S2.1
22.2: R16.2 S3.1 U1.36 | length 18.1
  Top Layer w0.254: R16.2@94.465,-70.335 94.465,-70.399 94.869,-70.399 94.869,-70.485 R16.2
  Top Layer w0.508: U1.36 84.201,-78.613 85.471,-77.343 86.344,-77.343 87.135,-76.552 87.135,-75.821 88.04,-74.917 88.884,-74.917 93.316,-70.485 R16.2 ; R16.2@94.465,-70.335 S3.1
22.3: R17.2 S4.1 U1.37 | length 11.7
  Top Layer w0.254: R17.2@94.465,-79.86 94.615,-79.86 94.615,-79.997 R17.2
  Top Layer w0.508: U1.37 86.008,-81.153 87.165,-79.997 94.615,-79.997 R17.2 ; R17.2@94.465,-79.86 S4.1
33.6: speed1.4 U1.24 | length 80.4
  Bottom Layer w0.381: v2(28.829,-90.607) 35.362,-84.074 39.624,-84.074 50.292,-94.742 77.462,-94.742 80.924,-91.28 80.924,-89.949 76.04,-85.065 74.709,-85.065 71.832,-82.187 71.832,-80.468 71.07,-79.706 70.286,-79.706 69.193,-78.613 U1.24
33.7: speed1.3 U1.25 | length 72.7
  Bottom Layer w0.381: v2(28.829,-84.907) 30.297,-83.439 39.847,-83.439 50.261,-93.853 77.597,-93.853 80.391,-91.059 80.391,-90.17 75.819,-85.598 73.914,-85.598 70.739,-82.423 70.739,-81.915 U1.25
33.9: Steer.1 U1.27 | length 95.4
  Top Layer w0.254: U1.27 72.238,-80.112 72.238,-39.487 74.397,-37.328 v1(74.397,-29.987)
  Bottom Layer w0.254: Steer.1 40.345,-12.573 52.629,-24.857 56.515,-24.857 57.023,-24.349 65.583,-24.349 71.222,-29.987 v1(74.397,-29.987)
33.10: R19.1 R20.1 U1.28 | length 29.9
  Top Layer w0.254: v1(58.039,-72.736) 58.055,-72.72 R20.1 v1(64.125,-69.459) ; v1(58.039,-66.208) R19.1
  Bottom Layer w0.254: v1(58.039,-72.736) v1(58.039,-66.208) ; v1(64.125,-69.459) U1.28
33.12: R12.2 S5.1 U1.30 | length 32.3
  Top Layer w0.254: R12.2 94.869,-58.42 R12.2@95.123,-58.42
  Top Layer w0.508: U1.30 75.819,-75.946 S5.1 R12.2@95.123,-58.42
33.13: R13.2 S5.2 U1.31 | length 35.2
  Top Layer w0.254: R13.2@97.663,-58.42 97.917,-58.42 R13.2
  Top Layer w0.381: U1.31 79.756,-79.756 79.756,-72.853 93,-59.609 95.509,-59.609 96.444,-58.674
  Top Layer w0.508: 96.444,-58.674 R13.2 ; R13.2@97.663,-58.42 S5.2
A0: OPA1_2.3 U1.21 | length 59.9
  Top Layer w0.254: U1.21 66.71,-80.102 71.323,-80.102 71.78,-79.644 71.78,-39.309 73.939,-37.15 73.939,-34.737 v1(72.771,-33.569)
  Bottom Layer w0.254: OPA1_2.3 69.555,-33.569 v1(72.771,-33.569)
A1: OPA1_2.4 U1.20 | length 51.1
  Top Layer w0.254: U1.20 63.119,-76.895 69.504,-70.51 69.504,-59.929 64.618,-55.042 64.618,-39.822 65.227,-39.212 66.452,-39.212 OPA1_2.4
A2: OPA1_2.5 U1.19 | length 53
  Top Layer w0.254: U1.19 64.618,-79.654 69.095,-79.654 69.71,-79.039 69.71,-70.879 69.91,-70.678 69.91,-59.344 69.303,-58.737 69.303,-39.754 72.898,-36.16 OPA1_2.5
A3: OPA1_2.6 U1.18 | length 55.8
  Top Layer w0.254: v1(70.485,-77.47) 70.485,-44.657 69.71,-43.881 69.71,-40.02 70.246,-39.484 70.565,-39.484 v1(73,-37.049)
  Bottom Layer w0.254: U1.18 61.722,-77.47 v1(70.485,-77.47) ; v1(73,-37.049) 73.695,-37.049 OPA1_2.6
A4: OPA2_2.3 U1.17 | length 52.9
  Top Layer w0.254: v1(50.089,-41.639) 49.378,-40.927 49.378,-39.868 49.784,-39.462 50.927,-39.462 v1(51.029,-39.563)
  Bottom Layer w0.254: v1(50.089,-41.639) 50.089,-41.849 49.378,-42.56 49.378,-51.247 59.538,-61.407 59.538,-80.112 U1.17 ; v1(51.029,-39.563) 51.029,-35.966 OPA2_2.3
A5: OPA2_2.4 U1.16 | length 62.3
  Top Layer w0.254: U1.16 61.376,-75.276 63.525,-75.276 69.097,-69.704 69.097,-60.564 61.683,-53.149 61.683,-39.17 v1(64.11,-36.744)
  Bottom Layer w0.254: OPA2_2.4 55.667,-36.744 v1(64.11,-36.744)
A6: OPA2_2.5 U1.15 | length 76.2
  Top Layer w0.254: v1(39.878,-38.903) 39.218,-39.563 39.218,-43.83 39.624,-44.237 43.282,-44.237 v1(47.315,-48.271)
  Bottom Layer w0.254: v1(39.878,-38.903) 39.878,-33.416 40.538,-32.756 54.219,-32.756 OPA2_2.5 ; v1(47.315,-48.271) 47.315,-64.633 56.744,-74.061 56.744,-79.858 U1.15
A7: OPA2_2.6 U1.14 | length 56.9
  Top Layer w0.254: v1(48.87,-67.224) 59.538,-56.556 59.538,-39.512 59.944,-39.106 60.985,-39.106 v1(63.83,-36.261)
  Bottom Layer w0.254: v1(48.87,-67.224) 55.499,-73.853 U1.14 ; OPA2_2.6 60.34,-36.337 63.754,-36.337 v1(63.83,-36.261)
A8: C22.2 R10.2 R11.1 U1.13 | length 72.3
  Top Layer w0.508: v2(9.652,-41.646) R11.1 R10.2
  Bottom Layer w0.508: v2(9.652,-41.646) 19.939,-51.933 19.939,-57.277 26.67,-64.008 36.703,-64.008 39.878,-67.183 45.847,-67.183 54.229,-75.565 54.229,-79.883 U1.13
A10: ADC.16 U1.12 | length 35.7
  Bottom Layer w0.508: U1.12 51.575,-79.997 51.575,-81.915 52.578,-82.918 52.578,-82.982 58.987,-82.982 64.885,-88.88 76.042,-88.88 78.023,-90.861 v2(79.629,-90.861)
A11: ADC.15 U1.11 | length 28.3
  Top Layer w0.254: U1.11 54.356,-82.55 77.018,-82.55 ADC.15
A12: ADC.14 U1.10 | length 35.7
  Bottom Layer w0.508: U1.10 49.149,-79.883 49.149,-82.245 50.546,-83.642 58.713,-83.642 64.611,-89.54 74.162,-89.54 75.483,-90.861 v2(77.089,-90.861)
A13: ADC.13 U1.9 | length 28.3
  Top Layer w0.254: U1.9 52.324,-83.058 74.986,-83.058 ADC.13
A16: ADC.12 U1.8 | length 36
  Bottom Layer w0.508: U1.8 46.736,-79.756 46.736,-80.647 46.723,-80.661 46.723,-83.146 47.879,-84.303 58.44,-84.303 64.338,-90.201 72.283,-90.201 72.943,-90.861 v2(74.549,-90.861)
A17: ADC.11 U1.7 | length 28.4
  Top Layer w0.254: U1.7 50.267,-83.541 61.04,-83.541 61.055,-83.525 62.643,-83.525 62.658,-83.541 63.58,-83.541 63.595,-83.525 65.183,-83.525 65.198,-83.541 66.12,-83.541 66.135,-83.525 67.723,-83.525 67.738,-83.541 68.66,-83.541 68.675,-83.525 72.913,-83.525 ADC.11
A20: ADC.10 U1.6 | length 35.6
  Bottom Layer w0.508: U1.6 44.196,-79.756 44.196,-80.647 44.183,-80.661 44.183,-82.41 46.736,-84.963 58.166,-84.963 64.064,-90.861 v2(72.009,-90.861)
A21: ADC.9 U1.5 | length 28.4
  Top Layer w0.254: U1.5 48.133,-83.947 61.208,-83.947 61.223,-83.932 62.475,-83.932 62.49,-83.947 63.748,-83.947 63.763,-83.932 65.015,-83.932 65.03,-83.947 66.288,-83.947 66.303,-83.932 67.555,-83.932 67.57,-83.947 68.828,-83.947 68.843,-83.932 70.78,-83.932 ADC.9
GND5V: ADC.1 ADC.3 ADC.5 ADC.7 C8.2 C9.1 C10.2 C11.1 C12.2 C13.1 C14.2 C15.1 C18.2 C19.1 FB2.2 FB3.1 FB4.1 ICM20602.2 OLED/TFT.2 Q1.1 R20.2 S1.2 S2.2 S3.2 S4.2 S5.3 S5.4 speed1.1 speed2.1 speed3.1 speed4.1 TTL.2 U1.1 U1.3 U4.2 U5.2 U6.2 W2UART.5 W2UART.6 | length 435.2
  Top Layer w0.254: speed3.1 34.29,-4.257 34.519,-4.486 41.123,-4.486 41.91,-3.698 44.45,-3.698 speed2.1 44.45,-2.225 44.679,-1.997 47.676,-1.997 47.803,-2.124 47.803,-3.444 v1(52.73,-8.372) ; C18.2 v1(54.051,-24.257) ; v1(54.102,-23.866) 55.362,-23.866 FB4.1 ; v1(83.515,-27.651) 84.074,-27.651 84.201,-27.524 W2UART.5 ; ICM20602.2 99.47,-40.288 99.47,-48.797
  Top Layer w0.381: Q1.1 57.15,-63.901 57.15,-68.586 v2(56.277,-69.459)
  Top Layer w0.508: FB2.2 22.133,-65.532 C8.2 ; U5.2 26.467,-47.295 C15.1 ; FB3.1 29.083,-46.482 27.559,-48.006 C15.1 ; U1.3 U1.1 36.505,-84.907 speed4.1 33.404,-84.907 32.047,-86.263 27.645,-86.263 speed1.1 ; C10.2 47.358,-90.17 ; U4.2 50.025,-87.504 C11.1 47.358,-90.17 ; v2(50.927,-74.676) 51.06,-74.676 v2(56.277,-69.459) ; C18.2 54.864,-24.257 C19.1 ; U6.2 56.073,-23.048 C19.1 ; FB4.1 57.277,-25.908 C19.1 ; ADC.7 ADC.5 ADC.3 ADC.1 61.016,-85.161 C13.1 56.007,-90.17 v2(54.991,-90.17) 47.358,-90.17 ; TTL.2 84.074,-32.314 W2UART.6 W2UART.5 ; S5.4 S5.3 99.47,-48.797 ; OLED/TFT.2 99.607,-13.318 99.607,-40.211 99.5,-40.318 ; ICM20602.2 99.5,-40.318 ; speed1.1 24.765,-86.431 24.765,-91.821 26.035,-93.091 v2(54.991,-93.091) 70.765,-93.091 70.79,-93.116 84.861,-93.116 99.164,-78.814 S4.2 S2.2 S3.2 S1.2 99.164,-59.936 99.695,-59.405 99.695,-40.513 99.5,-40.318 ; speed1.1 26.289,-70.45 C8.2 ; C8.2 29.743,-70.069 C9.1 33.401,-66.411 33.401,-64.008 27.813,-58.42 C14.2 27.178,-49.911 C15.1
  Bottom Layer w0.254: v1(52.73,-8.372) 52.73,-22.936 v1(54.051,-24.257) ; v1(54.102,-23.866) 54.277,-23.691 85.623,-23.691 85.9,-23.968 85.9,-25.266 v1(83.515,-27.651) ; TTL.2 84.772,-37.274 84.772,-37.988 85.213,-38.43 89.729,-38.43 90.162,-38.862 ICM20602.2
  Bottom Layer w0.508: U1.1 41.529,-79.883 41.529,-75.692 42.532,-74.689 43.278,-74.689 43.291,-74.676 v2(50.927,-74.676) ; v2(54.991,-93.091) v2(54.991,-90.17)
GND_6.5V: C4.2 C5.1 FB1.2 Steer.3 | length 37.2
  Top Layer w0.254: FB1.2 FB1.2@18.948,-35.042
  Top Layer w1.016: C4.2 21.346,-27.422 25.019,-23.749 31.52,-23.749 34.036,-21.233 Steer.3
  Top Layer w2.032: FB1.2@18.948,-35.042 21.463,-35.042 C5.1 20.726,-29.987 C4.2
GNDBAT: BAT.1 C2.1 C3.2 C6.2 C7.1 C22.1 FB1.1 FB2.1 Motor1.3 Motor1.4 Motor2.3 Motor2.4 Motor_1.2 Motor_2.2 P14.1 R11.2 U2.3 U2.5 U3.2 | length 206.2
  Top Layer w0.254: BAT.1 5.613,-57.775 5.74,-57.648 7.874,-57.648 ; C6.2 14.072,-65.649 C7.1 ; U2.3@20.193,-17.423 20.193,-17.555 U2.3
  Top Layer w2.032: BAT.1 15.992,-57.775 17.272,-59.055 U3.2 17.272,-64.897 FB2.1 17.79,-65.649 C7.1 10.312,-70.45 10.312,-86.639 Motor_2.2 18.542,-87.63 18.796,-87.884 ; 7.874,-57.648 7.874,-45.339 ; R11.2 C22.1 7.874,-45.339 ; Motor1.4 18.796,-87.884 ; Motor1.3 18.796,-87.884 ; U2.3@20.193,-17.423 18.82,-17.423 17.907,-16.51 17.907,-13.774 19.304,-12.377 ; U2.3 21.181,-17.456 23.946,-17.456 P14.1 ; U2.5 19.304,-12.377 ; Motor2.4 Motor2.3 26.797,-1.128 16.779,-1.128 15.621,-2.286 ; 7.874,-45.339 9.271,-45.339 16.764,-37.846 FB1.1 12.937,-31.215 10.827,-31.215 10.143,-31.899 10.143,-32.773 C2.1 7.01,-29.86 C3.2 7.01,-23.194 4.247,-23.194 3.563,-22.51 3.563,-9.256 10.533,-2.286 15.621,-2.286 ; 15.621,-2.286 Motor_1.2 19.304,-12.377
GNDCAM: C16.2 C17.1 Camera.4 Camera.14 FB3.2 | length 20.5
  Top Layer w0.254: FB3.2 FB3.2@29.464,-44.196
  Top Layer w0.508: FB3.2 29.083,-44.399 29.989,-45.306 29.989,-46.66 29.972,-46.677 29.972,-51.999 Camera.14 ; FB3.2@29.464,-44.196 29.464,-44.323 27.432,-42.291 C17.1 27.432,-40.132 C16.2 30.297,-39.624 Camera.4
GNDOP: C20.2 C21.1 FB4.2 OPA1_1.1 OPA1_1.6 OPA1_2.2 OPA2_1.1 OPA2_1.6 OPA2_2.2 电磁接口1.1 电磁接口1.6 电磁接口2.1 电磁接口2.6 | length 98.5
  Top Layer w0.508: FB4.2 59.563,-25.908 C21.1 63.754,-23.876 C20.2
  Top Layer w1.27: 电磁接口2.1 OPA2_1.6 48.387,-16.764 58.293,-16.764 59.309,-15.748 OPA2_1.1 ; OPA2_2.2 51.572,-32.883 62.929,-32.883 OPA1_2.2@65.278,-35.232 ; 电磁接口2.6 OPA2_1.1 ; C20.2 65.278,-25.4 ; OPA1_2.2 OPA1_2.2@65.278,-35.232 ; OPA2_1.1 OPA1_1.1 电磁接口1.6 64.275,-10.02 73.901,-10.02 电磁接口1.1 OPA1_1.6 73.533,-16.891 72.39,-16.891 69.977,-19.304 69.977,-23.876 68.453,-25.4 65.278,-25.4 ; OPA1_2.2@65.278,-35.232 65.278,-25.4
NetB1_1: B1.1 R18.2 | length 10.4
  Top Layer w0.508: R18.2 58.647,-67.892 58.997,-67.892 59.929,-68.824 B1.1
NetB1_2: B1.2 Q1.2 | length 10.4
  Top Layer w0.508: Q1.2 59.859,-61.224 B1.2
NetBAT_2: BAT.2 on/off.1 | length 7.9
  Top Layer w0.254: on/off.1 3.48,-43.053 3.48,-43.145 3.175,-43.145 on/off.1@3.175,-43.244
  Top Layer w2.032: BAT.2 on/off.1@3.175,-43.244
NetC6_1: C6.1 C7.2 D1.2 U3.1 | length 17
  Top Layer w0.254: C7.2@14.707,-63.465 14.275,-63.465 14.275,-63.871 C7.2
  Top Layer w2.032: D1.2 7.028,-64.946 C6.1 12.852,-62.83 ; C7.2@14.707,-63.465 14.072,-62.83 12.852,-62.83 ; U3.1 12.852,-62.83
NetL1_1: L1.1 U2.2 | length 8.6
  Top Layer w0.254: U2.2 22.225,-19.255 U2.2@22.225,-19.387 ; L1.1@27.642,-20.32 L1.1@27.642,-19.387
  Top Layer w1.524: U2.2@22.225,-19.387 L1.1@27.642,-19.387
  Top Layer w2.032: L1.1@27.642,-20.32 L1.1
NetOPA1_1_2: OPA1_1.2 电磁接口1.5 | length 3.4
  Top Layer w1.27: OPA1_1.2 电磁接口1.5
NetOPA1_1_3: OPA1_1.3 电磁接口1.4 | length 3.4
  Top Layer w1.27: OPA1_1.3 电磁接口1.4
NetOPA1_1_4: OPA1_1.4 电磁接口1.3 | length 3.4
  Top Layer w1.27: OPA1_1.4 电磁接口1.3
NetOPA1_1_5: OPA1_1.5 电磁接口1.2 | length 3.4
  Top Layer w1.27: OPA1_1.5 电磁接口1.2
NetOPA2_1_2: OPA2_1.2 电磁接口2.5 | length 3.4
  Top Layer w1.27: OPA2_1.2 电磁接口2.5
NetOPA2_1_3: OPA2_1.3 电磁接口2.4 | length 3.4
  Top Layer w1.27: OPA2_1.3 电磁接口2.4
NetOPA2_1_4: OPA2_1.4 电磁接口2.3 | length 3.4
  Top Layer w1.27: OPA2_1.4 电磁接口2.3
NetOPA2_1_5: OPA2_1.5 电磁接口2.2 | length 3.4
  Top Layer w1.27: OPA2_1.5 电磁接口2.2
NetP14_2: P14.2 U2.4 | length 10.2
  Top Layer w0.254: U2.4 22.15,-15.855 22.479,-15.526
  Top Layer w1.524: 22.479,-15.526 23.146,-15.526 24.092,-14.58 26,-14.58 27.93,-16.51 P14.2
NetQ1_3: Q1.3 R19.2 | length 5.7
  Top Layer w0.508: R19.2 55.87,-65.141 55.51,-64.781 55.51,-62.224 57.016,-60.717 Q1.3
VCC3V3: ADC.2 ADC.4 ADC.6 ADC.8 C12.1 C13.2 ICM20602.1 OLED/TFT.4 R12.1 R13.1 R14.1 R15.1 R16.1 R17.1 R18.1 speed1.2 speed2.2 speed3.2 speed4.2 U1.2 U1.4 U4.5 | length 278.7
  Top Layer w0.254: speed3.2 34.29,-7.788 35.509,-6.569 43.917,-6.569 44.45,-7.102 v1(44.45,-7.635) speed2.2 ; U4.5 53.594,-86.554 54.416,-87.376 C12.1 ; v1(93.04,-28.209) 93.04,-14.722 93.853,-13.909 OLED/TFT.4 v1(93.853,-7.635) ; 96.203,-61.786 96.393,-61.786 ; 96.393,-61.976 96.393,-61.786 ; R13.1 96.584,-61.786 96.393,-61.786
  Top Layer w0.508: speed1.2 28.011,-92.329 34.727,-92.329 speed4.2 38.171,-92.329 60.381,-92.329 v2(61.849,-90.861) ADC.4 ADC.6 ADC.8 71.064,-92.456 83.947,-92.456 R17.1 R15.1 R16.1 R14.1 96.393,-61.976 ; U1.2 U1.4 ; R18.1 56.14,-67.437 53.975,-67.437 U1.4 ; v2(57.404,-86.995) 53.487,-86.995 U4.5 51.836,-85.344 47.627,-85.344 44.183,-81.899 44.183,-79.997 U1.4 ; R12.1 96.203,-61.786 ; 96.584,-61.786 R13.1 98.171,-60.198 97.968,-60.198 98.839,-59.326 98.839,-52.821 93.947,-47.928 93.947,-45.499 ICM20602.1
  Bottom Layer w0.254: v1(44.45,-7.635) v1(93.853,-7.635) ; v1(93.04,-28.209) 94.793,-29.962 98.552,-29.962 99.085,-30.495 99.085,-40.361 ICM20602.1
  Bottom Layer w0.508: v2(57.404,-86.995) 57.404,-89.662 58.603,-90.861 v2(61.849,-90.861)
VCC5V: C8.1 C9.2 C10.1 C11.2 C14.1 C15.2 C18.1 C19.2 only_1.1 TTL.1 U3.3 U4.1 U4.3 U5.1 U5.3 U6.1 U6.3 W2UART.7 | length 159.6
  Top Layer w0.254: U5.3 27.417,-45.832 27.417,-45.293 v1(27.813,-44.897) ; v2(46.355,-87.376) C10.1 ; v1(48.815,-23.194) only_1.1 ; U6.3 57.15,-24.653 v1(57.328,-24.831) ; TTL.1 86.614,-34.788 85.928,-34.102 85.928,-29.708 86.741,-28.895 W2UART.7
  Top Layer w0.508: U3.3 C8.1@25.044,-60.95 ; 27.417,-45.832 27.051,-45.466 25.908,-45.466 25.517,-45.857 U5.1 25.517,-47.889 C15.2 25.019,-48.387 C14.1 25.019,-60.925 C8.1@25.044,-60.95 ; v2(32.131,-65.903) 28.677,-62.449 C8.1 C8.1@25.044,-60.95 ; C10.1 48.374,-87.376 C11.2 49.197,-86.554 U4.1 50.994,-86.554 51.308,-86.868 51.308,-88.138 50.992,-88.454 U4.3 ; only_1.1 51.943,-22.225 C18.1 54.61,-21.463 C19.2 U6.1 57.729,-22.098 58.116,-22.485 58.116,-23.289 57.861,-23.543 57.861,-23.704 57.444,-23.704 U6.3
  Bottom Layer w0.254: v1(27.813,-44.897) 48.815,-23.895 v1(48.815,-23.194) ; v1(57.328,-24.831) 65.227,-24.831 73.558,-33.162 85.374,-33.162 86.614,-34.402 TTL.1
  Bottom Layer w0.508: v2(32.131,-65.903) 32.131,-75.057 39.751,-82.677 41.656,-82.677 v2(46.355,-87.376)
VCC_6.5V: C4.1 C5.2 L1.2 P14.3 Steer.2 | length 39.3
  Top Layer w0.254: C5.2 26.042,-32.883 26.042,-32.773
  Top Layer w1.27: 26.042,-32.773 26.79,-32.773 28.346,-31.217 C4.1 31.6,-27.295 L1.2 38.575,-19.538 37.579,-18.542 37.579,-13.576 Steer.2 35.039,-11.036 27.826,-11.036 P14.3
VCCBAT: C2.2 C3.1 D1.1 Motor_1.1 Motor_2.1 on/off.2 on/off.3 R10.1 U2.1 | length 185.1
  Top Layer w0.254: 7.747,-35.433 v1(10.897,-35.433) 11.547,-35.433 11.573,-35.179 11.675,-34.194 ; R10.1@7.849,-37.176 7.874,-37.176 R10.1 ; v1(9.611,-34.194) 11.675,-34.194 ; v1(10.897,-27.422) C3.1 14.63,-27.407 14.63,-21.565 v1@14.732,-21.463 ; 11.811,-34.194 11.675,-34.194 ; C2.2 11.675,-34.194 ; v1(14.605,-21.463) v1@14.732,-21.463 ; 20.574,-21.463 v1@14.732,-21.463 ; U2.1 15.24,-20.955 v1@14.732,-21.463
  Top Layer w2.032: on/off.2 on/off.3 5.397,-35.179 11.811,-35.179 11.811,-34.194 ; D1.1 3.175,-87.122 Motor_2.1 ; 7.747,-35.433 7.747,-37.074 R10.1@7.849,-37.176 ; Motor_1.1 11.684,-24.476 C3.1 14.63,-27.407 20.574,-21.463
  Bottom Layer w0.254: on/off.2@3.365,-40.44 v1(9.611,-34.194) ; v1(10.897,-35.433) v1(10.897,-27.422) ; 14.605,-27.432 v1(14.605,-21.463)
  Bottom Layer w2.032: on/off.3 13.144,-27.432 14.605,-27.432 ; on/off.2@3.365,-40.44 4.604,-40.44 6.593,-42.429 6.593,-59.191 3.683,-62.101 Motor_2.1
VCCCAM: C16.1 C17.2 Camera.16 U5.5 | length 26.8
  Top Layer w0.254: Camera.16 31.496,-56.007 v1(31.496,-55.21)
  Top Layer w0.508: v2(23.368,-54.864) 23.368,-46.004 U5.5 25.654,-43.718 C17.2 25.146,-41.656 C16.1
  Bottom Layer w0.254: v1(31.496,-55.21) 31.623,-55.337 v2(31.623,-56.007)
  Bottom Layer w0.508: v2(23.368,-54.864) 24.511,-56.007 v2(31.623,-56.007)
VCCOP: C20.1 C21.2 ONLY.1 U6.5 | length 8.1
  Top Layer w0.508: U6.5 C21.2 62.103,-21.59 C20.1 66.802,-21.59 ONLY.1
VCCOPA: ONLY.2 only_1.2 OPA1_2.1 OPA2_2.1 | length 74.6
  Top Layer w0.254: OPA1_2.1 61.605,-36.439 48.539,-36.439 48.057,-35.956 48.057,-32.545 53.815,-26.787 58.115,-26.787 58.395,-26.508 58.395,-23.764 59.131,-23.028 66.462,-23.028 ONLY.2
  Top Layer w1.27: only_1.2 49.784,-32.131 OPA2_2.1 48.895,-37.592 60.452,-37.592 OPA1_2.1
pads on no net: Camera.10 ICM20602.7 ICM20602.8 P10.0 P11.0 P12.0 P13.0 speed1.5 speed1.6 speed2.5 speed2.6 speed3.5 speed3.6 speed4.5 speed4.6 U1.22 U1.23 U1.26 U1.29 U1.32 U1.33 U1.42 U1.43 U1.45 U1.47 U1.48 U1.49 U1.50 U1.51 U1.52 U1.53 U1.64 U1.65 U1.66 U1.69 U1.70 U1.71 U1.72 U1.73 U1.78 U1.79 U1.80 U1.107 U1.109 U1.110 U1.111 U1.112 U1.113 U1.114 U1.115 U1.116 U1.117 U1.118 U1.119 U1.120 U1.121 U1.122 U2.0 U3.0 U4.4 U5.4 U6.4 W2UART.2 W2UART.8

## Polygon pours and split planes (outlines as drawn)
GND5V on Top Layer "Top Layer-No Net" (solid, remove dead copper, pour order 15): -0.127,-100.066 ccw(c0,-100.066) 0.046,-100.185 ccw(c0.127,-100.086) 0.127,-100.213 100.33,-100.213 ccw(c100.33,-100.086) 100.457,-100.086 100.457,-0.01 ccw(c100.33,-0.01) 100.284,0.109 ccw(c100.203,0.01) 100.203,0.137 0,0.137 ccw(c0,0.01) -0.127,0.01
GNDCAM on Top Layer "Top Layer-GNDCAM" (solid, remove dead copper, pour order 11): 22.86,-44.897 23.033,-45.071 30.394,-45.071 30.394,-56.601 30.226,-56.769 30.607,-57.15 39.03,-57.15 39.03,-35.22 36.512,-32.703 32.409,-36.806 23.241,-36.806
GND_6.5V on Top Layer "Top Layer-GND_6.5V" (solid, remove dead copper, pour order 9): 44.196,-10.353 43.893,-10.051 17.89,-10.051 17.89,-36.051 19.939,-38.1 44.831,-38.1 44.831,-10.845 44.196,-10.21
GNDOP on Top Layer "Top Layer-GNDOP" (solid, remove dead copper, pour order 7): 43.434,-7.432 75.504,-7.432 77.089,-9.017 76.581,-9.525 76.581,-39.106 45.166,-39.106 43.434,-37.374
GNDBAT on Top Layer "Top Layer-GNDBAT" (solid, remove dead copper, pour order 5): 0,0 31.115,0 30.988,-0.127 30.988,-10.287 27.051,-10.287 26.162,-11.176 26.162,-22.987 25.955,-23.194 20.367,-23.194 17.907,-25.654 17.907,-57.785 19.05,-58.928 19.05,-82.677 20.701,-84.328 20.701,-100.076 0,-100.076
GND5V on Bottom Layer "GND5V_L02_P018" (solid, remove dead copper, pour order 18): -0.127,-100.066 ccw(c0,-100.066) 0.046,-100.185 ccw(c0.127,-100.086) 0.127,-100.213 100.33,-100.213 ccw(c100.33,-100.086) 100.457,-100.086 100.457,-0.01 ccw(c100.33,-0.01) 100.284,0.109 ccw(c100.203,0.01) 100.203,0.137 0,0.137 ccw(c0,0.01) -0.127,0.01
GNDOP on Bottom Layer "GNDOP_L02_P017" (solid, remove dead copper, pour order 17): 43.434,-7.432 75.504,-7.432 77.089,-9.017 76.581,-9.525 76.581,-39.106 45.166,-39.106 43.434,-37.374
GNDBAT on Bottom Layer "GNDBAT_L02_P016" (solid, remove dead copper, pour order 16): 0,0 31.115,0 30.988,-0.127 30.988,-10.287 27.051,-10.287 26.162,-11.176 26.162,-22.987 25.955,-23.194 20.367,-23.194 17.907,-25.654 17.907,-57.785 19.05,-58.928 19.05,-82.677 20.701,-84.328 20.701,-100.076 0,-100.076

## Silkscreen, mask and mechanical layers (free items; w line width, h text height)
Top Overlay:
  text "TC264学习用开发板V1.0" at 17.399,-98.679 h7.5
Mechanical 13:
  lines w0.254: 0,-100.066 0,0.01 100.203,0.01 ; 0.127,-100.086 100.33,-100.086 100.33,-0.01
